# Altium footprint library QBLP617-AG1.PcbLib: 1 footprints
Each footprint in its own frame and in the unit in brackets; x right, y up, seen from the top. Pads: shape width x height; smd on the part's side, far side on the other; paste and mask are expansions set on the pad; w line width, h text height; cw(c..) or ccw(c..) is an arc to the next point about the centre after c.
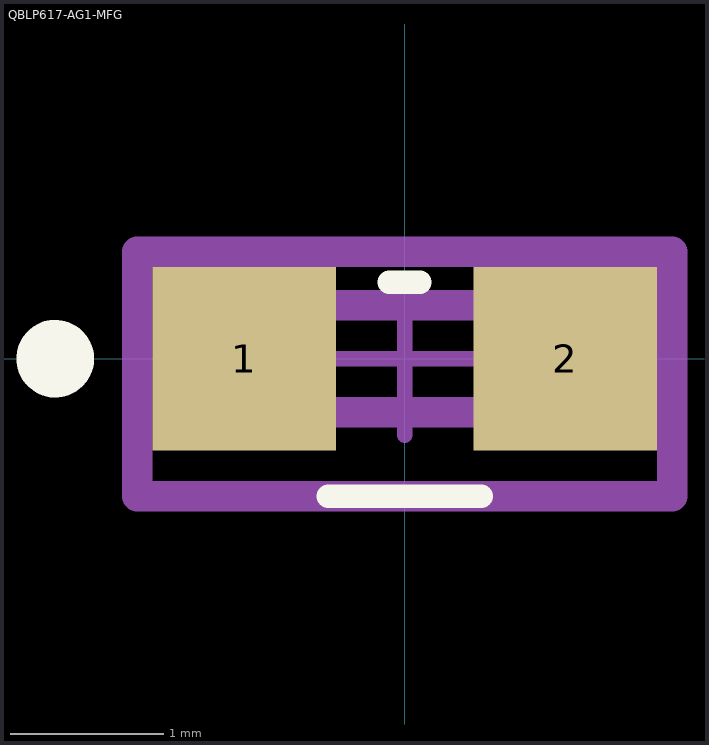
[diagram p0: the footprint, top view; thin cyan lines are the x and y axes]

## QBLP617-AG1-MFG [mm]
pads (2):
  rect 1.2x1.2 smd paste+0 mask+0: 1(-1.05,0) 2(1.05,0)
Top Overlay:
  circle w0.254: c-2.286,0 r0.127
  lines w0.152: -0.5,-0.9 0.5,-0.9 ; -0.1,0.5 0.1,0.5
Mechanical 5:
  lines w0.2: -1.75,-0.9 1.75,-0.9 1.75,0.7 -1.75,0.7 -1.75,-0.9
  text ".Designator" at 0.254,-0.066 h1
Mechanical 13:
  lines w0.2: -0.85,-0.35 0.85,-0.35 0.85,0.35 -0.85,0.35 -0.85,-0.35
Mechanical 15:
  lines w0.2: -1.75,-0.9 1.75,-0.9 1.75,0.7 -1.75,0.7 -1.75,-0.9
  text "LENS SIDE" at -1.1,-1.394 h0.5
Mechanical 16:
  lines w0.1: -0.5,0 0.5,0 ; 0,-0.5 0,0.5
3D body "QBLP617.step": height 0.6, standoff 0, extent -0.8,-0.85 0.8,0.35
